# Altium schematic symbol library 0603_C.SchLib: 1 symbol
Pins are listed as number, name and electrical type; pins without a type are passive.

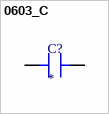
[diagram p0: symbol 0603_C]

## 0603_C
designator C?
footprint 0603
pins: 1, 2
